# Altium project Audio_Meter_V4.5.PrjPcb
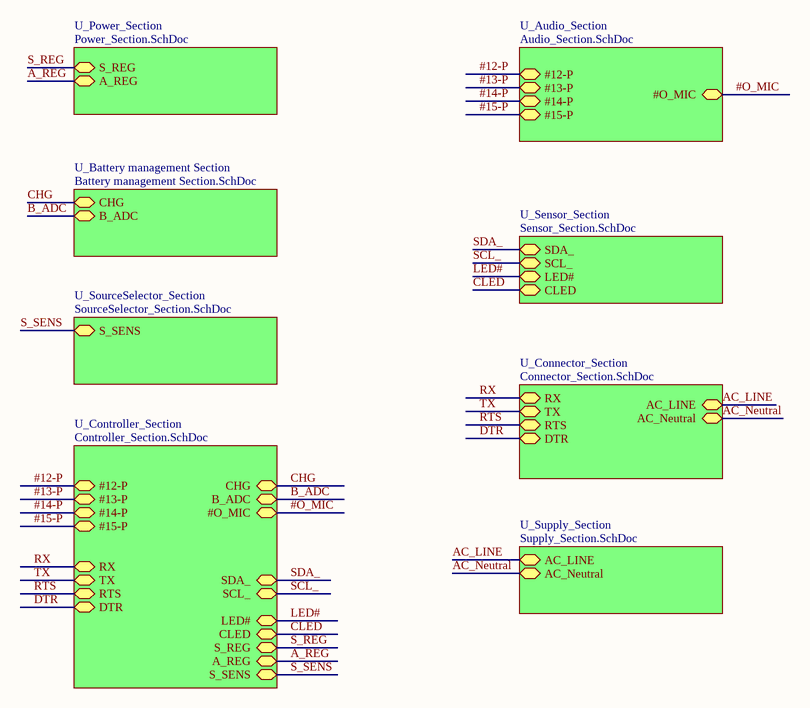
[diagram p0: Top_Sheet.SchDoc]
9 sheets, 115 parts. Net scope: hierarchical (ports join the sheet entries above them; power ports are global).
Board file: latest_Audio_Meter_V4.5.PcbDoc
Sheets:
  Top_Sheet.SchDoc
    U_Audio_Section = Audio_Section.SchDoc
    U_Connector_Section = Connector_Section.SchDoc
    U_Supply_Section = Supply_Section.SchDoc
    U_Battery management Section = Battery management Section.SchDoc
    U_Power_Section = Power_Section.SchDoc
    U_Controller_Section = Controller_Section.SchDoc
    U_SourceSelector_Section = SourceSelector_Section.SchDoc
    U_Sensor_Section = Sensor_Section.SchDoc

## Sheet Top_Sheet.SchDoc
size A; DocumentNumber: 1; SheetNumber: 1; SheetTotal: 8

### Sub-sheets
U_Audio_Section = Audio_Section.SchDoc: #O_MIC (bidir), #13-P (bidir), #14-P (bidir), #12-P (bidir), #15-P (bidir)
U_Battery management Section = Battery management Section.SchDoc: B_ADC (bidir), CHG (bidir)
U_Connector_Section = Connector_Section.SchDoc: RX (bidir), TX (bidir), RTS (bidir), DTR (bidir), AC_LINE (bidir), AC_Neutral (bidir)
U_Controller_Section = Controller_Section.SchDoc: B_ADC (bidir), CHG (bidir), #12-P (bidir), #13-P (bidir), #14-P (bidir), #15-P (bidir), #O_MIC (bidir), RX (bidir), TX (bidir), RTS (bidir), DTR (bidir), SDA_ (bidir), SCL_ (bidir), S_SENS (bidir), CLED (bidir), LED# (bidir), A_REG (bidir), S_REG (bidir)
U_Power_Section = Power_Section.SchDoc: A_REG (bidir), S_REG (bidir)
U_Sensor_Section = Sensor_Section.SchDoc: SDA_ (bidir), SCL_ (bidir), CLED (bidir), LED# (bidir)
U_SourceSelector_Section = SourceSelector_Section.SchDoc: S_SENS (bidir)
U_Supply_Section = Supply_Section.SchDoc: AC_LINE (bidir), AC_Neutral (bidir)

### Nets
#12-P: sheet U_Audio_Section/#12-P, sheet U_Controller_Section/#12-P
#13-P: sheet U_Audio_Section/#13-P, sheet U_Controller_Section/#13-P
#14-P: sheet U_Audio_Section/#14-P, sheet U_Controller_Section/#14-P
#15-P: sheet U_Audio_Section/#15-P, sheet U_Controller_Section/#15-P
#O_MIC: sheet U_Audio_Section/#O_MIC, sheet U_Controller_Section/#O_MIC
A_REG: sheet U_Power_Section/A_REG, sheet U_Controller_Section/A_REG
AC_LINE: sheet U_Connector_Section/AC_LINE, sheet U_Supply_Section/AC_LINE
AC_Neutral: sheet U_Connector_Section/AC_Neutral, sheet U_Supply_Section/AC_Neutral
B_ADC: sheet U_Battery management Section/B_ADC, sheet U_Controller_Section/B_ADC
CHG: sheet U_Battery management Section/CHG, sheet U_Controller_Section/CHG
CLED: sheet U_Controller_Section/CLED, sheet U_Sensor_Section/CLED
DTR: sheet U_Connector_Section/DTR, sheet U_Controller_Section/DTR
LED#: sheet U_Controller_Section/LED#, sheet U_Sensor_Section/LED#
RTS: sheet U_Connector_Section/RTS, sheet U_Controller_Section/RTS
RX: sheet U_Connector_Section/RX, sheet U_Controller_Section/RX
S_REG: sheet U_Power_Section/S_REG, sheet U_Controller_Section/S_REG
S_SENS: sheet U_Controller_Section/S_SENS, sheet U_SourceSelector_Section/S_SENS
SCL_: sheet U_Controller_Section/SCL_, sheet U_Sensor_Section/SCL_
SDA_: sheet U_Controller_Section/SDA_, sheet U_Sensor_Section/SDA_
TX: sheet U_Connector_Section/TX, sheet U_Controller_Section/TX

## Sheet Audio_Section.SchDoc
size A; DocumentNumber: 6; SheetNumber: 6; SheetTotal: 8
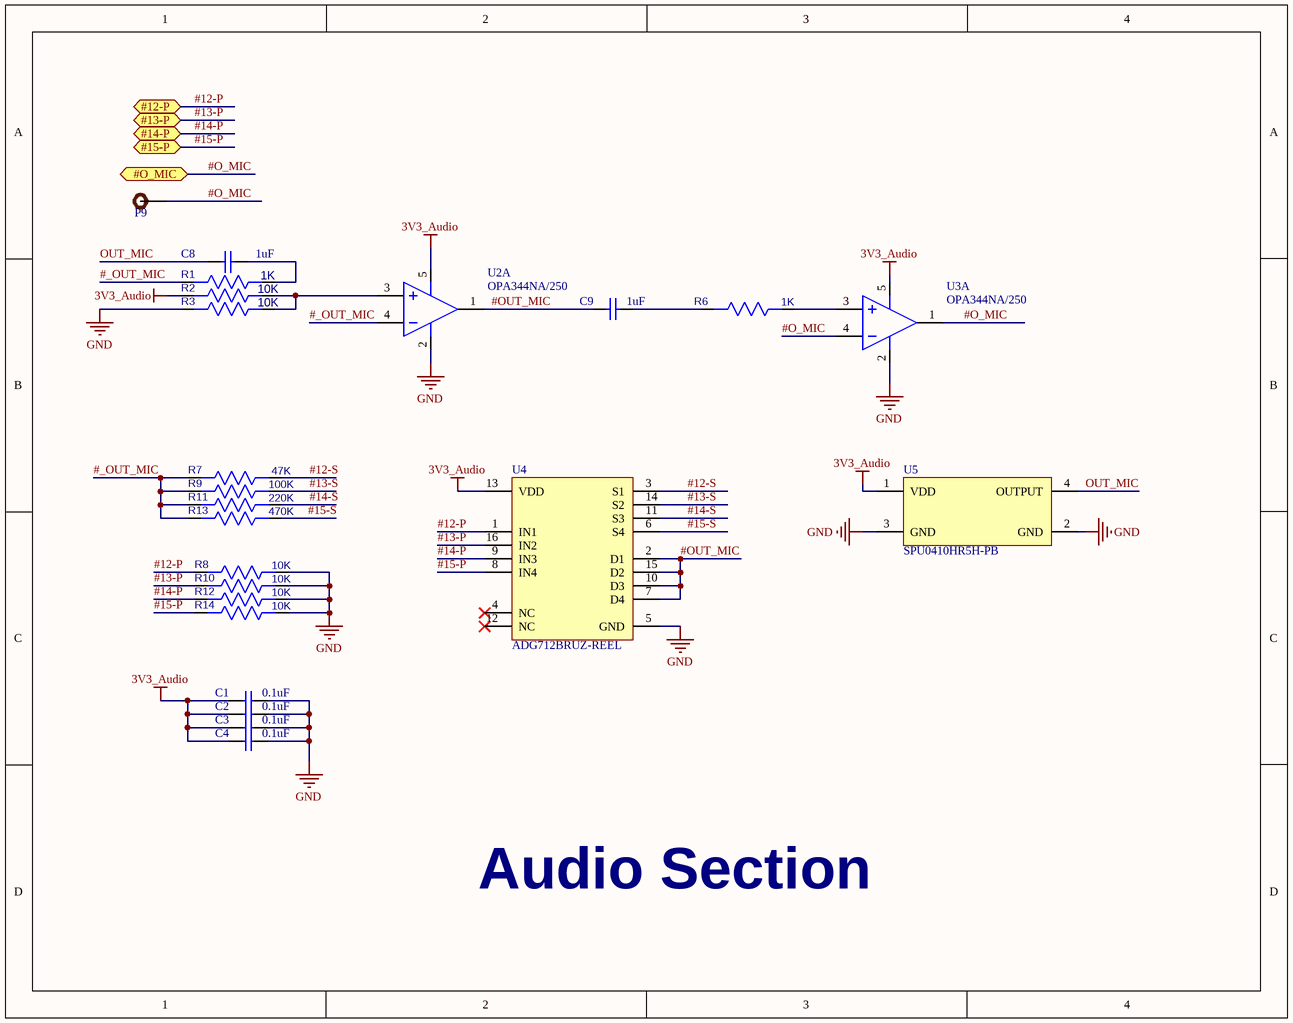
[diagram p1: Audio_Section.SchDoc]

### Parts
C1  0.1uF  [Cap0603]
C2  0.1uF  [Cap0603]
C3  0.1uF  [Cap0603]
C4  0.1uF  [Cap0603]
C8  Capacitance: 1uF  [Cap1206]  (hidden comment: 1206YC105K4T2A)
C9  Capacitance: 1uF  [Cap1206]  (hidden comment: 1206YC105K4T2A)
P9  TEST POINT  [TEST POINT]  (value not drawn)
R1  1K  [RES 0805]
R2  10K  [RES 0805]
R3  10K  [RES 0805]
R6  1K  [RES 0805]
R7  47K  [RES 0805]
R8  10K  [RES 0805]
R9  100K  [RES 0805]
R10  10K  [RES 0805]
R11  220K  [RES 0805]
R12  10K  [RES 0805]
R13  470K  [RES 0805]
R14  10K  [RES 0805]
U2A  OPA344NA/250  [SOT23-5]
U3A  OPA344NA/250  [SOT23-5]
U4  ADG712BRUZ-REEL  [16-TSSOP]
U5  SPU0410HR5H-PB  [SPU0410HR5H-PB]

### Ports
#12-P (bidir), #13-P (bidir), #14-P (bidir), #15-P (bidir), #O_MIC (bidir)

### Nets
3V3_Audio: C1.1 C2.1 C3.1 C4.1 R2.2 U2A.5(V+) U3A.5(V+) U4.13(VDD) U5.1(VDD)
GND: C1.2 C2.2 C3.2 C4.2 R3.2 R8.1 R10.1 R12.1 R14.1 U2A.2(V-) U3A.2(V-) U4.5(GND) U5.2(GND) U5.3(GND)
#12-P: R8.2 U4.1(IN1) ; port #12-P
#12-S: R7.1 U4.3(S1)
#13-P: R10.2 U4.16(IN2) ; port #13-P
#13-S: R9.1 U4.14(S2)
#14-P: R12.2 U4.9(IN3) ; port #14-P
#14-S: R11.1 U4.11(S3)
#15-P: R14.2 U4.8(IN4) ; port #15-P
#15-S: R13.1 U4.6(S4)
#_OUT_MIC: R1.2 R7.2 R9.2 R11.2 R13.2 U2A.4(IN-)
#O_MIC: P9.1 U3A.1(OUT) U3A.4(IN-) ; port #O_MIC
#OUT_MIC: C9.1 U2A.1(OUT) U4.2(D1) U4.7(D4) U4.10(D3) U4.15(D2)
OUT_MIC: C8.1 U5.4(OUTPUT)
NetC8_2: C8.2 R1.1
NetC9_2: C9.2 R6.2
NetR2_1: R2.1 R3.1 U2A.3(IN+)
NetR6_1: R6.1 U3A.3(IN+)

Not connected (* = marked no-connect by the designer): U4 4(NC)* 12(NC)*

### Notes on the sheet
- Audio Section

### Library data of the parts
C1-C4 = CC0603ZRY5V9BB104: CAP CER 0.1UF 50V Y5V 0603; Manufacturer: Yageo; Capacitance: 100nF; Tolerance: 80%
C8 C9 = 1206YC105K4T2A: CAP CER 1UF 16V X7R 1206; Manufacturer: Kyocera AVX; Tolerance: 10%
P9 = TEST POINT: Test Point ON
R1 R6 = ERJ-P06J102V: RES SMD 1K OHM 5% 1/2W 0805; Manufacturer: Panasonic; Resistance: 1kR; Power Rating: 500mW; Voltage Rating: 400V; Temperature Coefficient: 200ppm/°C; Voltage Rating (DC): 150V
R2 R3 R8 R10 R12 R14 = ERJ-P06J103V: RES SMD 10K OHM 5% 1/2W 0805; Manufacturer: Panasonic; Resistance: 10kR; Power Rating: 500mW; Voltage Rating: 400V; Temperature Coefficient: 200ppm/°C; Voltage Rating (DC): 150V
R7 = CRCW080547K0FKEAHP: RES SMD 47K OHM 1% 1/3W 0805; Manufacturer: Vishay; Power Rating: 330mW; Resistance: 47kR; Temperature Coefficient: 100ppm/°C; Voltage Rating: 150V; Max Power Dissipation: 333mW
R9 = ERJ-P06J104V: RES SMD 100K OHM 5% 1/2W 0805; Manufacturer: Panasonic; Power Rating: 500mW; Voltage Rating: 400V; Resistance: 100kR; Temperature Coefficient: 200ppm/°C; Max Power Dissipation: 250mW; Voltage Rating (DC): 150V
R11 = ERJ-P06J224V: RES SMD 220K OHM 5% 1/2W 0805; Manufacturer: Panasonic; Resistance: 220kR; Power Rating: 500mW; Voltage Rating: 150V; Temperature Coefficient: 200ppm/°C
R13 = CRCW0805470KFKEAHP: RES SMD 470K OHM 1% 1/3W 0805; Manufacturer: Vishay Dale; Resistance: 470kR; Power Rating: 330mW; Temperature Coefficient: 100ppm/°C; Max Power Dissipation: 500mW
U2A U3A = OPA344NA/250: IC OPAMP GP 1 CIRCUIT SOT23-5; Manufacturer: Texas Instruments; Nominal Supply Current: 250uA; Bandwidth: 1MHz; Min Supply Voltage: 2.7V; Max Supply Voltage: 5.5V; Voltage Gain: 122dB; Common Mode Rejection Ratio: 76dB; Number of Channels: 1; Slew Rate: 0.8V/µs; Max I/O Voltage: 1mV; Input Bias Current: 10pA; Power Supply Rejection Ratio (PSRR): 90.46dB; Output Current per Channel: 15mA; Quiescent Current: 250mA
U4 = ADG712BRUZ-REEL: IC SWITCH QUAD SPST 16TSSOP; Manufacturer: Analog Devices; Max Supply Voltage: 5.5V; Min Supply Voltage: 1.8V; Number of Inputs: 4; Max Power Dissipation: 5uW; On-State Resistance: 4R; -3db Bandwidth: 200MHz; Max Supply Current: 1uA; Turn-On Delay Time: 11ns; Turn-Off Delay Time: 6ns; Operating Supply Current: 1nA; Power Dissipation: 430mW; Supply Type: Single; Polarity: Non-Inverting; High Level Output Current: 30mA; Interface: Parallel
U5 = SPU0410HR5H-PB: SPU-TOP MIC IOT FOCUSED MIC; Manufacturer: Knowles; Shape: Rectangular; Impedance: 300R; Voltage Rating: 3.6V; Direction: Omnidirectional; Operating Supply Current: 250uA; Signal to Noise Ratio (SNR): 59dB; Output Type: Analog

## Sheet Connector_Section.SchDoc
size A; DocumentNumber: 8; SheetNumber: 8; SheetTotal: 8
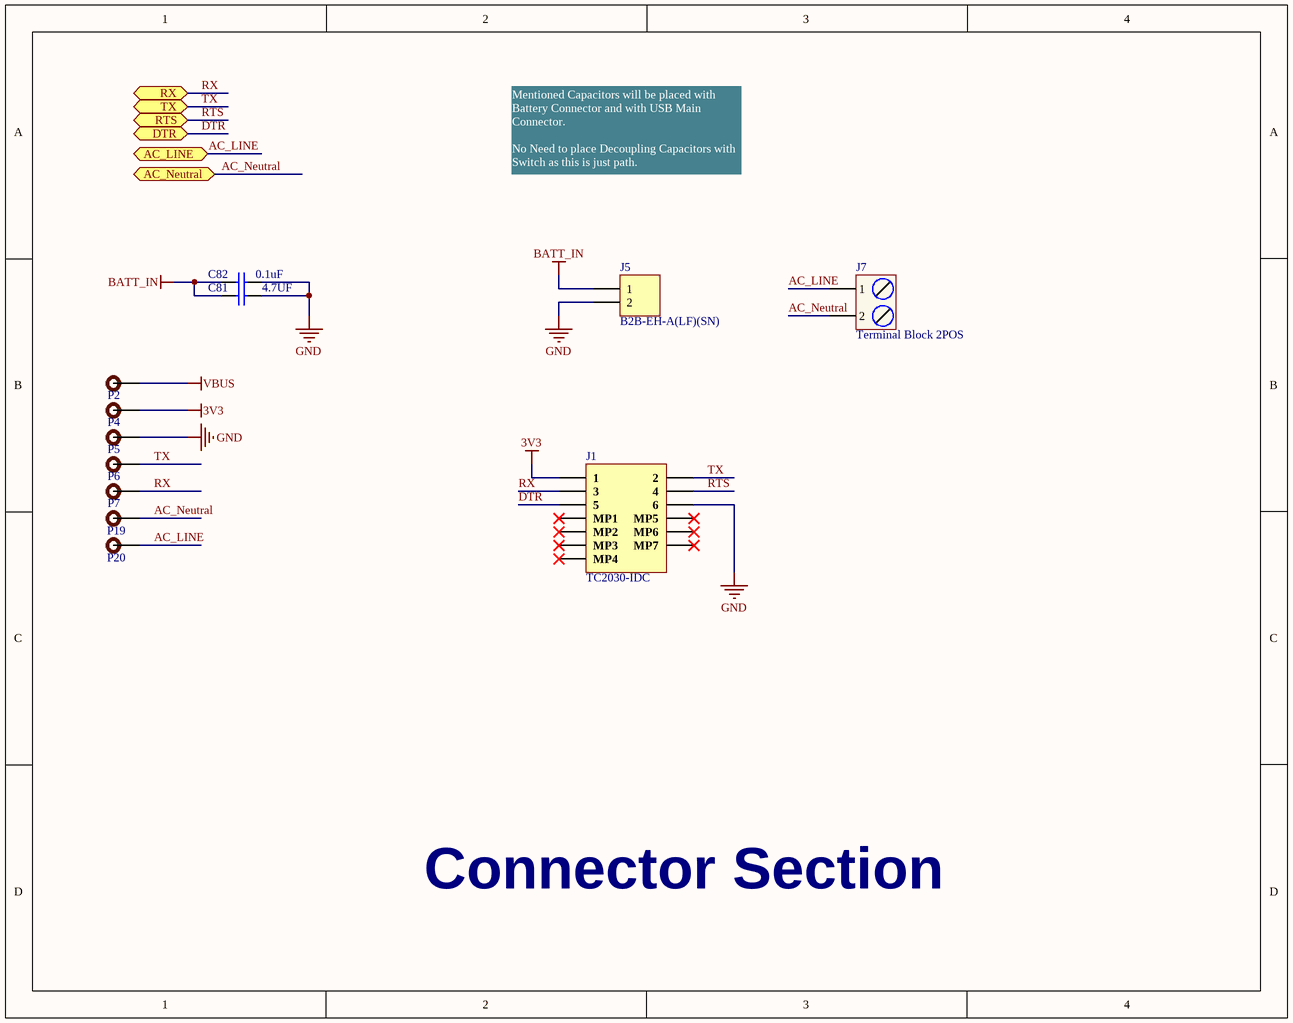
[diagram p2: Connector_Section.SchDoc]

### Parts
C81  4.7UF  [Cap0805]
C82  0.1uF  [Cap0603]
J1  TC2030-IDC  [TC2030-IDC]
J5  B2B-EH-A(LF)(SN)  [B2B-EH-A(LF)(SN)]
J7  Terminal Block 2POS  [Terminal Block 2P]
P2  TEST POINT  [TEST POINT]  (value not drawn)
P4  TEST POINT  [TEST POINT]  (value not drawn)
P5  TEST POINT  [TEST POINT]  (value not drawn)
P6  TEST POINT  [TEST POINT]  (value not drawn)
P7  TEST POINT  [TEST POINT]  (value not drawn)
P19  TEST POINT  [TEST POINT]  (value not drawn)
P20  TEST POINT  [TEST POINT]  (value not drawn)

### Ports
AC_LINE (bidir), AC_Neutral (bidir), DTR (bidir), RTS (bidir), RX (bidir), TX (bidir)

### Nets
3V3: J1.1 P4.1
BATT_IN: C81.1 C82.1 J5.1
GND: C81.2 C82.2 J1.6 J5.2 P5.1
VBUS: P2.1
AC_LINE: J7.1 P20.1 ; port AC_LINE
AC_Neutral: J7.2 P19.1 ; port AC_Neutral
DTR: J1.5 ; port DTR
RTS: J1.4 ; port RTS
RX: J1.3 P7.1 ; port RX
TX: J1.2 P6.1 ; port TX

Not connected (* = marked no-connect by the designer): J1 MP1* MP2* MP3* MP4* MP5* MP6* MP7*

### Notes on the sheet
- Mentioned Capacitors will be placed with Battery Connector and with USB Main Connector.
  No Need to place Decoupling Capacitors with Switch as this is just path.
- Connector Section

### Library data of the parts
C81 = C0805C475K4PACTU: CAP CER 4.7UF 16V 10% X5R 0805; Manufacturer: KEMET; Dielectric Material: Ceramic
C82 = CC0603ZRY5V9BB104: as C1 on sheet Audio_Section
J1 = TC2030-IDC: CABLE ADAPTER 6 POS; Manufacturer: Tag-Connect
J5 = B2B-EH-A(LF)(SN): CONN HEADER VERT 2POS 2.5MM; Manufacturer: JST; Current Rating: 3A; Voltage Rating: 250V; Contact Resistance: 20mR; Number of Positions: 2; Connector Type: Male Pin,Plug; Gender: Male
J7 = Terminal Block 2POS: TERMINAL BLOCK 2POS 5.08MM SIDE; Manufacturer: TE Connectivity; Manufacturer P/N: 1776493-2
P2 P4-P7 P19 P20 = TEST POINT: Test Point ON

## Sheet Supply_Section.SchDoc
size A4
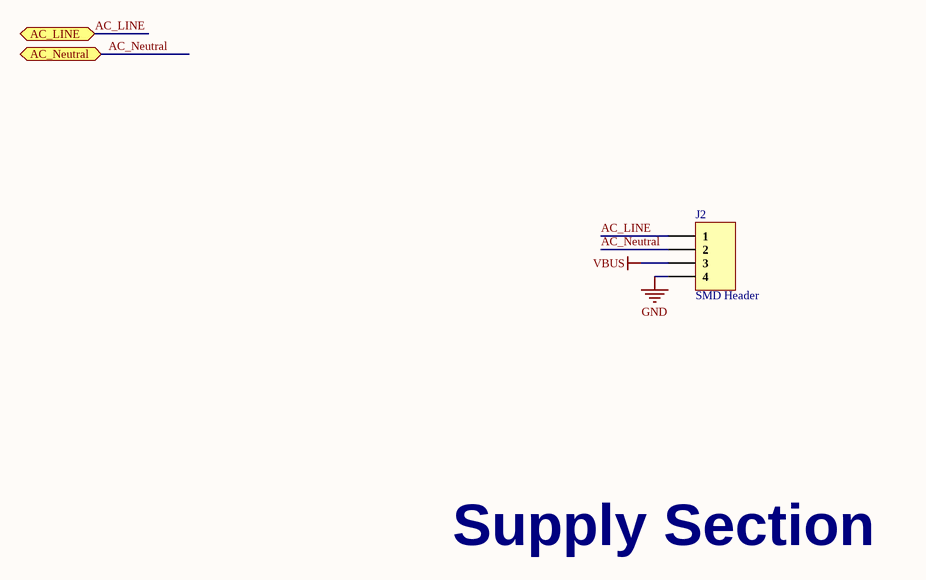
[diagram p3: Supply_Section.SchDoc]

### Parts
J2  SMD Header  [SMD Header]

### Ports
AC_LINE (bidir), AC_Neutral (bidir)

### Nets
GND: J2.4
VBUS: J2.3
AC_LINE: J2.1 ; port AC_LINE
AC_Neutral: J2.2 ; port AC_Neutral

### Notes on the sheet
- Supply Section

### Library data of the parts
J2 = SMD Header: According to module demension

## Sheet Battery management Section.SchDoc
size A; DocumentNumber: 4; SheetNumber: 4; SheetTotal: 8
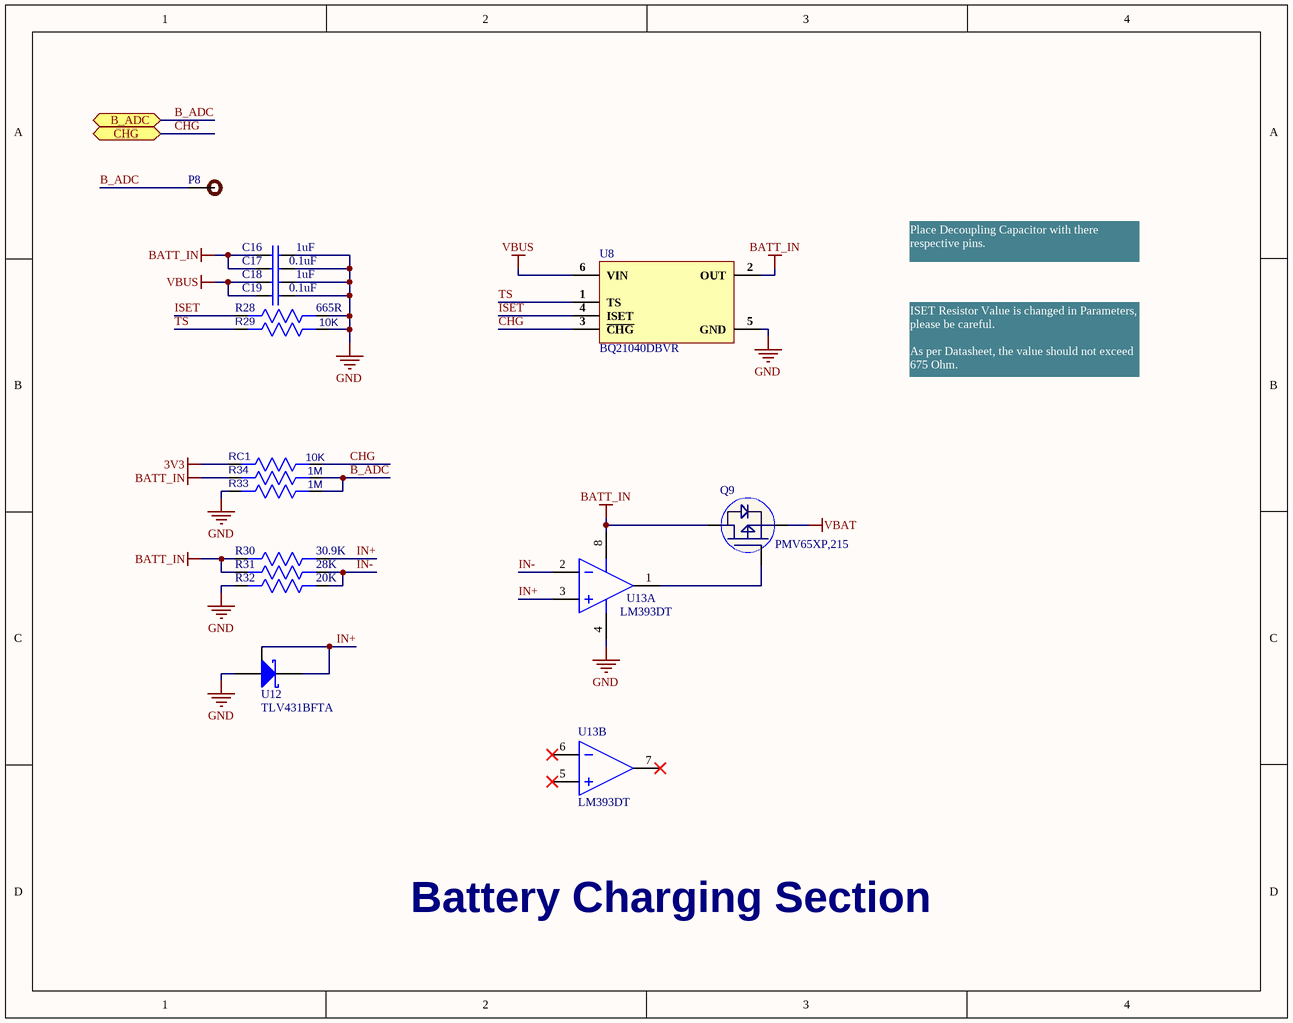
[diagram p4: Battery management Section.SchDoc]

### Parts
C16  1uF  [Cap0805]
C17  0.1uF  [Cap0603]
C18  1uF  [Cap0805]
C19  0.1uF  [Cap0603]
P8  TEST POINT  [TEST POINT]  (value not drawn)
Q9  PMV65XP,215  [SOT-23]
R28  665R  [Res0402]
R29  10K  [RES 0805]
R30  30.9K  [Res0402]
R31  28K  [Res-0201]
R32  20K  [Res-0201]
R33  1M  [RES 0805]
R34  1M  [RES 0805]
RC1  10K  [RES 0805]
U8  BQ21040DBVR  [SOT-23-6]
U12  TLV431BFTA  [SOT-23]
U13  LM393DT  [LM393DT]  (parts A,B of 2)

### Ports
B_ADC (bidir), CHG (bidir)

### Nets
3V3: RC1.2
BATT_IN: C16.1 C17.1 Q9.3(D) R30.2 R31.2 R34.2 U8.2(OUT) U13.8(V+)
GND: C16.2 C17.2 C18.2 C19.2 R28.1 R29.1 R32.2 R33.2 U8.5(GND) U12.3(ANODE) U13.4(V-)
VBAT: Q9.2(S)
VBUS: C18.1 C19.1 U8.6(VIN)
B_ADC: P8.1 R33.1 R34.1 ; port B_ADC
CHG: RC1.1 U8.3(~{CH}~{G}) ; port CHG
IN+: R30.1 U12.1(REF) U12.2(CATHODE) U13.3(IN1+)
IN-: R31.1 R32.1 U13.2(IN1-)
ISET: R28.2 U8.4(ISET)
TS: R29.2 U8.1(TS)
NetQ9_1: Q9.1(G) U13.1(OUT1)

Not connected (* = marked no-connect by the designer): U13 5(IN2+)* 6(IN2-)* 7(OUT2)*

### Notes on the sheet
- Place Decoupling Capacitor with there respective pins.
- ISET Resistor Value is changed in Parameters, please be careful.
  As per Datasheet, the value should not exceed 675 Ohm.
- Battery Charging Section

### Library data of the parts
C16 C18 = CL21B105KOFNNNG: CAP CER 1UF 16V X7R 0805; Manufacturer: Samsung; Material: Ceramic; Tolerance: 10%
C17 C19 = CC0603ZRY5V9BB104: as C1 on sheet Audio_Section
P8 = TEST POINT: Test Point ON
Q9 = PMV65XP,215: MOSFET P-CH 20V 2.8A SOT-23; Manufacturer: Nexperia
R28 = RC0402FR-07665RL: RES SMD 665 OHM 1% 1/16W 0402; Manufacturer: Yageo; Temperature Coefficient: 100ppm/°C; Power Rating: 62.5mW; Voltage Rating: 50V; Max Power Dissipation: 63mW
R29 RC1 = ERJ-P06J103V: as R2 on sheet Audio_Section
R30 = AC0402FR-0730K9L: RES SMD 30.9K OHM 1% 1/16W 0402; Manufacturer: Yageo; Power Rating: 62.5mW; Resistance: 30.9kR; Voltage Rating: 50V; Temperature Coefficient: 100ppm/°C; Max Power Dissipation: 63mW
R31 = AC0201FR-0728KL: RES SMD 28K OHM 1% 1/20W 0201; Manufacturer: Yageo; Resistance: 28kR; Max Power Dissipation: 50mW; Temperature Coefficient: 200ppm/°C
R32 = AC0201FR-0720KL: RES SMD 20K OHM 1% 1/20W 0201; Manufacturer: Yageo; Resistance: 20kR; Max Power Dissipation: 50mW; Temperature Coefficient: 200ppm/°C
R33 R34 = ERJ-P06J105V: RES SMD 1M OHM 5% 1/2W 0805; Manufacturer: Panasonic; Resistance: 1MR; Power Rating: 500mW; Voltage Rating: 400V; Temperature Coefficient: 200ppm/°C; Voltage Rating (DC): 150V
U8 = BQ21040DBVR: IC BAT CHG LI-ION 1 CELL SOT23-6; Manufacturer: Texas Instruments; Number of Cells: 1; Fault Protection: Over Voltage,Over Temperature,Short Circuit; Interface: USB,SPI; Output Type: Analog Current/Voltage; Max Charge Current: 800mA; Battery Pack Voltage: 4.2V; Max Supply Voltage: 6.45V; Number of Bits: 16; Number of D/A Converters: 4; Settling Time: 30us; Differential Output: No
U12 = TLV431BFTA: IC VREF SHUNT 18V 0.5% SOT23; Manufacturer: Diodes Zetex; Max Input Voltage: 20V; Max Output Current: 15mA; Reference Type: Shunt,Adjustable; Min Output Voltage: 1.24V; Cathode Current: 100uA; Output Type: Adjustable
U13 = LM393DT: IC COMPARATOR LP DUAL 8-SOIC; Manufacturer: STMicroelectronics; Nominal Supply Current: 1mA; Voltage Gain: 106.02dB; Min Supply Voltage: 2V; Max Supply Voltage: 36V; Min Dual Supply Voltage: 1V; Max Dual Supply Voltage: 18V; Number of Channels: 2; Output Current: 18mA; Quiescent Current: 2.5mA; Input Offset Voltage (Vos): 5mV; Input Bias Current: 250nA; Output Current per Channel: 100pA; Response Time: 1.3us; Output Type: TTL; Operating Supply Voltage: 28V; Dual Supply Voltage: 9V; Max Power Dissipation: 710mW; Natural Thermal Resistance: 125°C/W

## Sheet Power_Section.SchDoc
size A4; DocumentNumber: 2; SheetNumber: 2; SheetTotal: 8
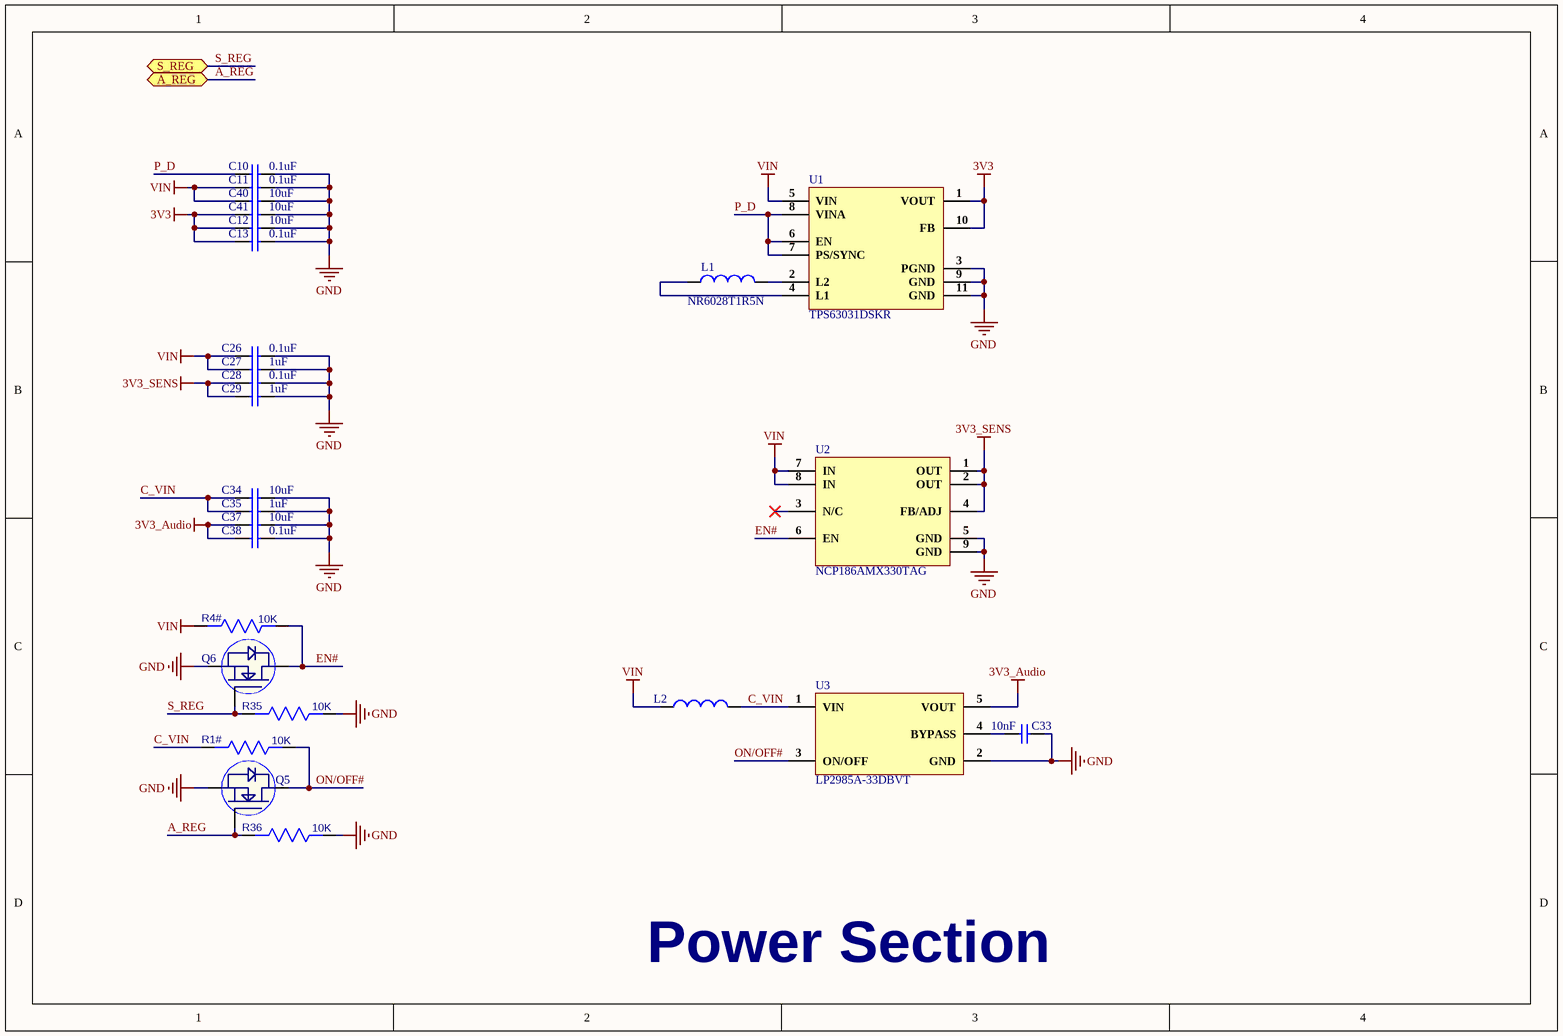
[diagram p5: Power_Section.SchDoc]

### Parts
C10  0.1uF  [Cap0603]
C11  0.1uF  [Cap0603]
C12  10uF  [Cap0603]
C13  0.1uF  [Cap0603]
C26  0.1uF  [Cap0603]
C27  1uF  [Cap0805]
C28  0.1uF  [Cap0603]
C29  1uF  [Cap0805]
C33  10nF  [CAP 0201]
C34  10uF  [Cap0603]
C35  1uF  [Cap0805]
C37  10uF  [Cap0603]
C38  0.1uF  [Cap0603]
C40  10uF  [Cap0603]
C41  10uF  [Cap0603]
L1  NR6028T1R5N  [NR6028T1R5N]
L2  BLM18SG121TN1D  [IND 0603]  (value not drawn)
Q5  BSS138LT1G  [SOT-23]  (value not drawn)
Q6  BSS138LT1G  [SOT-23]  (value not drawn)
R1#  10K  [RES 0805]
R4#  10K  [RES 0805]
R35  10K  [RES 0805]
R36  10K  [RES 0805]
U1  TPS63031DSKR  [TPS63031DSKR]
U2  NCP186AMX330TAG  [NCP186AMX330TAG]
U3  LP2985A-33DBVT  [SOT23-5]

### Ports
A_REG (bidir), S_REG (bidir)

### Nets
3V3: C12.1 C13.1 C41.1 U1.1(VOUT) U1.10(FB)
3V3_Audio: C37.1 C38.1 U3.5(VOUT)
3V3_SENS: C28.1 C29.1 U2.1(OUT) U2.2(OUT) U2.4(FB/ADJ)
GND: C10.2 C11.2 C12.2 C13.2 C26.2 C27.2 C28.2 C29.2 C33.2 C34.2 C35.2 C37.2 C38.2 C40.2 C41.2 Q5.2(S) Q6.2(S) R35.2 R36.2 U1.3(PGND) U1.9(GND) U1.11(GND) U2.5(GND) U2.9(GND) U3.2(GND)
VIN: C11.1 C26.1 C27.1 C40.1 L2.1 R4#.2 U1.5(VIN) U2.7(IN) U2.8(IN)
A_REG: Q5.1(G) R36.1 ; port A_REG
C_VIN: C34.1 C35.1 L2.2 R1#.2 U3.1(VIN)
EN#: Q6.3(D) R4#.1 U2.6(EN)
ON/OFF#: Q5.3(D) R1#.1 U3.3(ON/OFF)
P_D: C10.1 U1.6(EN) U1.7(PS/SYNC) U1.8(VINA)
S_REG: Q6.1(G) R35.1 ; port S_REG
NetC33_1: C33.1 U3.4(BYPASS)
NetL1_1: L1.1 U1.4(L1)
NetL1_2: L1.2 U1.2(L2)

Not connected (* = marked no-connect by the designer): U2 3(N/C)*

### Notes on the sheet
- Power Section

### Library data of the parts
C10 C11 C13 C26 C28 C38 = CC0603ZRY5V9BB104: as C1 on sheet Audio_Section
C12 C34 C37 C40 C41 = C1608X5R1E106M080AC: CAP CER 10UF 25V X5R 0603; Manufacturer: TDK; Dielectric Material: Ceramic; Tolerance: 20%
C27 C29 C35 = CL21B105KOFNNNG: as C16 on sheet Battery management Section
C33 = UMK063BJ103KP-F: CAP CER 10000PF 50V X5R 0201; Manufacturer: Taiyo Yuden; Tolerance: 10%
L1 = NR6028T1R5N: FIXED IND 1.5UH 4.2A 20.8 MOHM; Manufacturer: Taiyo Yuden; Manufacturer Part Number: NR6028T470M; Core Material: Ferrite; Tolerance: 20%; Current Rating: 920mA; Saturation Current: 950mA; Shielding: Shielded; Self Resonant Frequency: 8MHz; Inductance: 47uh; DC Resistance (DCR): 390mR; Test Frequency: 100kHz
L2 = BLM18SG121TN1D: FERRITE BEAD 120 OHM 0603 1LN; Manufacturer: Murata; Material: Steel,Ferrite; Tolerance: 25%; Impedance: 120R; DC Resistance (DCR): 25mR; Max DC Current: 3A; Number of Lines: 1; Test Frequency: 100MHz; Shielding: Unshielded
Q5 Q6 = BSS138LT1G: MOSFET N-CH 50V 200MA SOT-23; Manufacturer: ON Semiconductor; Gate to Source Voltage (Vgs): 20V; Nominal Vgs: 1.5V; Rds On Max: 3.5R; Input Capacitance: 50pF; Number of Elements: 1; Max Power Dissipation: 225mW; Turn-Off Delay Time: 20ns; Element Configuration: Single
R1# R4# R35 R36 = ERJ-P06J103V: as R2 on sheet Audio_Section
U1 = TPS63031DSKR: Conv DC-DC 1.8V to 5.5V Non-Inv/Inv/Step Up/Step Down Single-Out 3.3V 0.8A 10-Pin WSON; Manufacturer: Texas Instruments; Switching Frequency: 2.4MHz; Output Current: 800mA; Number of Outputs: 1; Synchronous Rectifier: Yes; Quiescent Current: 25uA; Output Type: Fixed; Efficiency: 96%; Topology: Buck-Boost; Output Configuration: Positive
U2 = NCP186AMX330TAG: IC REG LINEAR 3.3V 1A 8XDFN; Manufacturer: ON Semiconductor; Dropout Voltage: 95mV; Number of Regulators: 1; Min Current Limit: 1.1A
U3 = LP2985A-33DBVT: IC REG LINEAR 3.3V 150MA SOT23-5; Manufacturer: Texas Instruments; Number of Outputs: 1; Min Input Voltage: 2.2V; Max Input Voltage: 16V; Dropout Voltage: 280mV; Input Bias Current: 850uA; Polarity: Positive; Output Voltage Accuracy: 1%; Output Type: Fixed

## Sheet Controller_Section.SchDoc
size A; DocumentNumber: 5; SheetNumber: 5; SheetTotal: 8
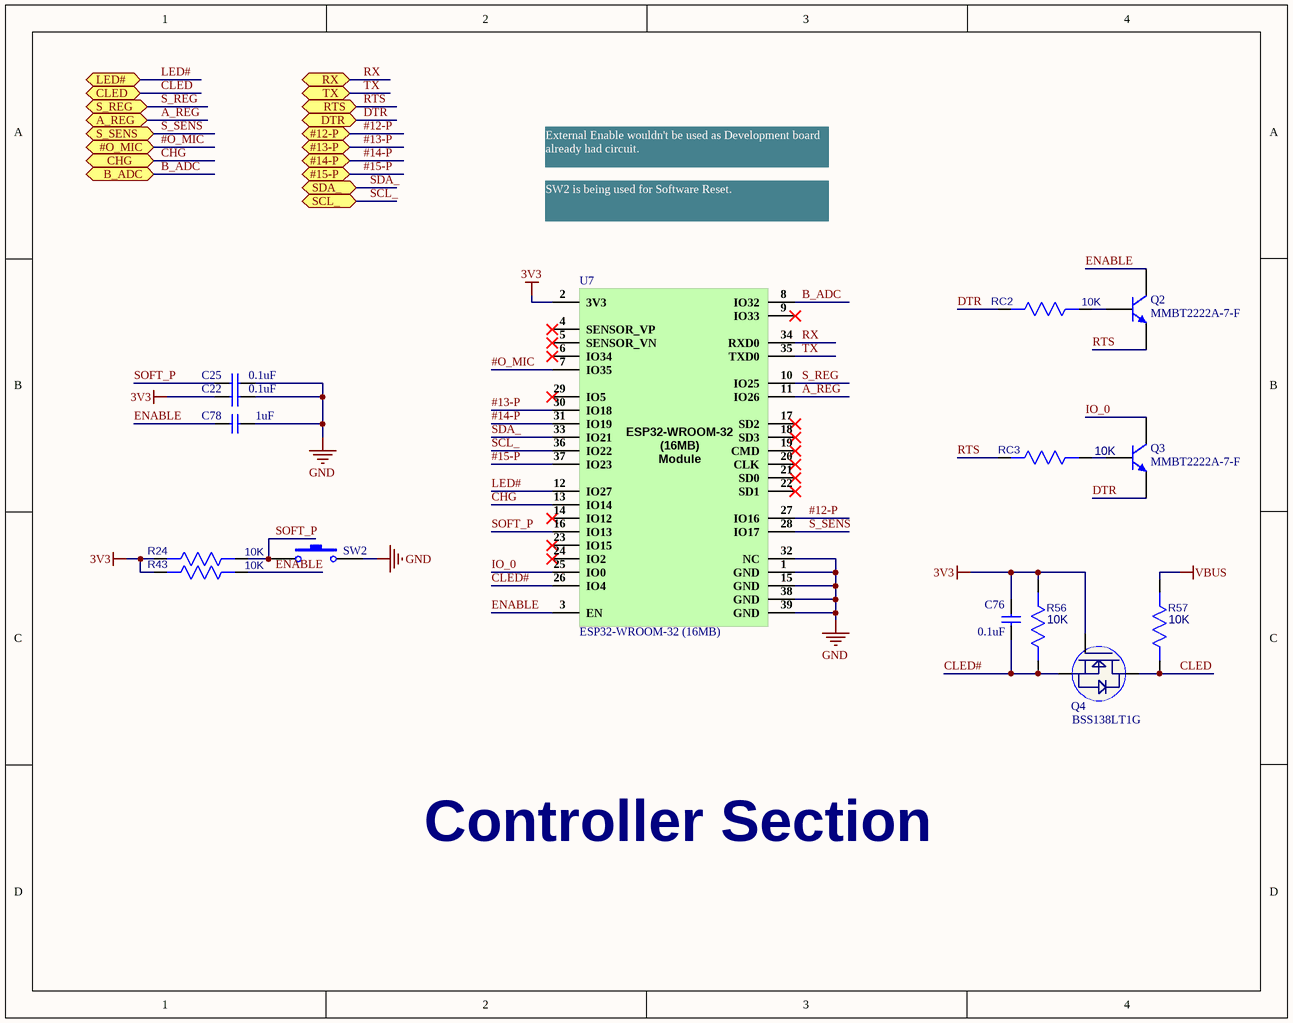
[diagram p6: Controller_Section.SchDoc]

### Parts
C22  0.1uF  [Cap0603]
C25  0.1uF  [Cap0603]
C76  0.1uF  [Cap0603]
C78  1uF  [Cap0805]
Q2  MMBT2222A-7-F  [SOT-23]
Q3  MMBT2222A-7-F  [SOT-23]
Q4  BSS138LT1G  [SOT-23]
R24  10K  [RES 0805]
R43  10K  [RES 0805]
R56  10K  [RES 0805]
R57  10K  [RES 0805]
RC2  10K  [RES 0805]
RC3  10K  [RES 0805]
SW2  Switch  [KSS221GLFS]  (value not drawn)
U7  ESP32-WROOM-32 (16MB)  [ESP32-WROOM-32 (16MB)]

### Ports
#12-P (bidir), #13-P (bidir), #14-P (bidir), #15-P (bidir), #O_MIC (bidir), A_REG (bidir), B_ADC (bidir), CHG (bidir), CLED (bidir), DTR (bidir), LED# (bidir), RTS (bidir), RX (bidir), S_REG (bidir), S_SENS (bidir), SCL_ (bidir), SDA_ (bidir), TX (bidir)

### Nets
3V3: C22.1 C76.1 Q4.1(G) R24.2 R43.2 R56.1 U7.2(3V3)
GND: C22.2 C25.2 C78.2 SW2.2 U7.1(GND) U7.15(GND) U7.32(NC) U7.38(GND) U7.39(GND)
VBUS: R57.1
#12-P: U7.27(IO16) ; port #12-P
#13-P: U7.30(IO18) ; port #13-P
#14-P: U7.31(IO19) ; port #14-P
#15-P: U7.37(IO23) ; port #15-P
#O_MIC: U7.7(IO35) ; port #O_MIC
A_REG: U7.11(IO26) ; port A_REG
B_ADC: U7.8(IO32) ; port B_ADC
CHG: U7.13(IO14) ; port CHG
CLED: Q4.3(D) R57.2 ; port CLED
CLED#: C76.2 Q4.2(S) R56.2 U7.26(IO4)
DTR: Q3.2(E) RC2.2 ; port DTR
ENABLE: C78.1 Q2.3(C) R43.1 U7.3(EN)
IO_0: Q3.3(C) U7.25(IO0)
LED#: U7.12(IO27) ; port LED#
RTS: Q2.2(E) RC3.2 ; port RTS
RX: U7.34(RXD0) ; port RX
S_REG: U7.10(IO25) ; port S_REG
S_SENS: U7.28(IO17) ; port S_SENS
SCL_: U7.36(IO22) ; port SCL_
SDA_: U7.33(IO21) ; port SDA_
SOFT_P: C25.1 R24.1 SW2.1 U7.16(IO13)
TX: U7.35(TXD0) ; port TX
NetQ2_1: Q2.1(B) RC2.1
NetQ3_1: Q3.1(B) RC3.1

Not connected (* = marked no-connect by the designer): U7 4(SENSOR_VP)* 5(SENSOR_VN)* 6(IO34)* 9(IO33)* 14(IO12)* 17(SD2)* 18(SD3)* 19(CMD)* 20(CLK)* 21(SD0)* 22(SD1)* 23(IO15)* 24(IO2)* 29(IO5)*

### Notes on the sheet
- External Enable wouldn't be used as Development board already had circuit.
- SW2 is being used for Software Reset.
- Controller Section

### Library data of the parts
C22 C25 C76 = CC0603ZRY5V9BB104: as C1 on sheet Audio_Section
C78 = CL21B105KOFNNNG: as C16 on sheet Battery management Section
Q2 Q3 = MMBT2222A-7-F: TRANS NPN 40V 0.6A SMD SOT23-3; Manufacturer: Diodes; Max Power Dissipation: 300mW; Collector Base Voltage (VCBO): 75V; Max Collector Current: 600mA; hFE Min: 100; Frequency: 300MHz; Number of Elements: 1; Emitter Base Voltage (VEBO): 6V; Collector Emitter Saturation Voltage: 1V; Power Dissipation: 350mW; Element Configuration: Single; Current: 1A
Q4 = BSS138LT1G: as Q5 on sheet Power_Section
R24 R43 R56 R57 RC2 RC3 = ERJ-P06J103V: as R2 on sheet Audio_Section
SW2 = KSS221GLFS: Tactile Switch SPST-NO Side Actuated Surface Mount, Right Angle; Manufacturer: ITT C&K; Mechanical Life: 100000Cycles; Throw Configuration: SPST; Operating Force: 2N; Max Current Rating: 50mA; Max Voltage Rating (DC): 32V; Contact Resistance: 100mR; Power Rating: 1W; Illumination Type: Non-Illuminated,Illuminated; Insulation Resistance: 1GR; Switch Travel: 0.3mm; Switch Function: Off-Mom; Actuator Length: 0.8mm; IP Rating: IP40
U7 = ESP32-WROOM-32 (16MB): WIFI MODULE 128MBITS SPI FLASH; Manufacturer: Espressif Systems; Manufacturer Part Number: ESP32-WROOM-32D(16MB); Interface: I2C,SPI,GPIO,PWM,SDIO,UART; Frequency: 2.5GHz; Data Rate: 150Mbps; Sensitivity: -98dBm; Memory Size: 536KB

## Sheet SourceSelector_Section.SchDoc
size A4
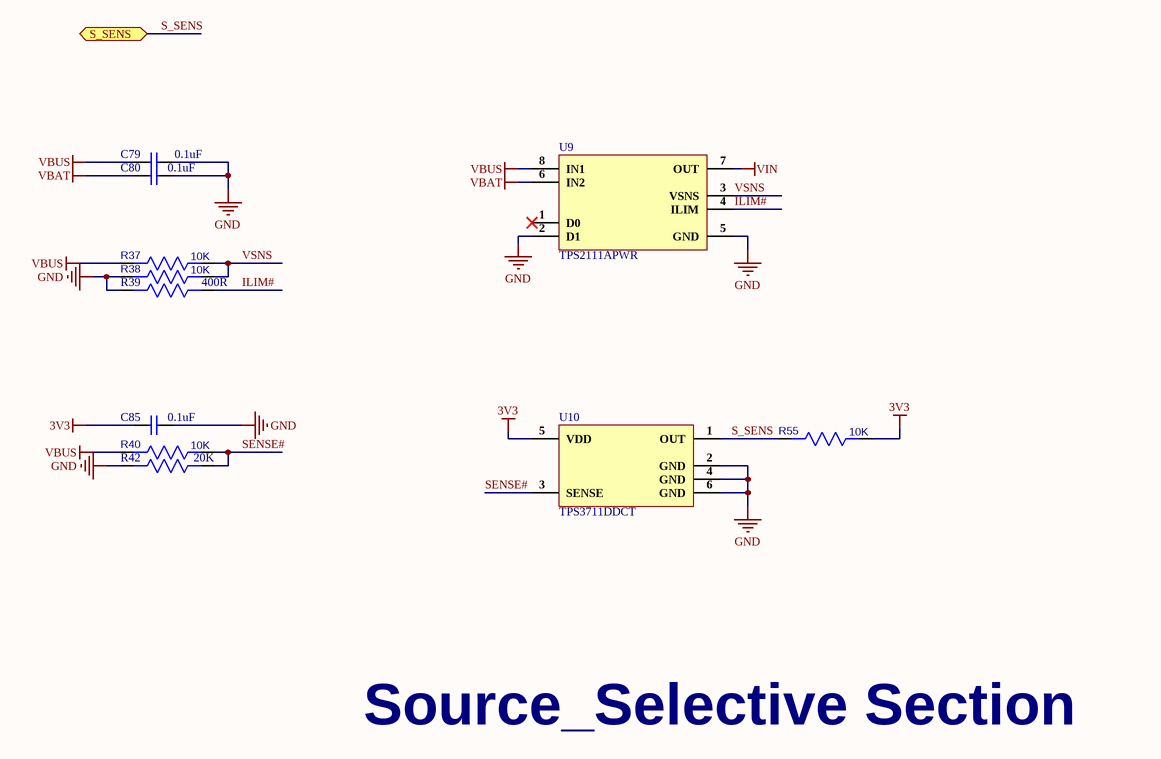
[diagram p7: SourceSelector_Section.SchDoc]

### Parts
C79  0.1uF  [Cap0603]
C80  0.1uF  [Cap0603]
C85  0.1uF  [Cap0603]
R37  10K  [RES 0805]
R38  10K  [RES 0805]
R39  400R  [Res0603]
R40  10K  [RES 0805]
R42  20K  [Res-0201]
R55  10K  [RES 0805]
U9  TPS2111APWR  [8-TSSOP]
U10  TPS3711DDCT  [SOT-23-6]

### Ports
S_SENS (bidir)

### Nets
3V3: C85.1 R55.1 U10.5(VDD)
GND: C79.2 C80.2 C85.2 R38.1 R39.2 R42.2 U9.2(D1) U9.5(GND) U10.2(GND) U10.4(GND) U10.6(GND)
VBAT: C80.1 U9.6(IN2)
VBUS: C79.1 R37.2 R40.2 U9.8(IN1)
VIN: U9.7(OUT)
ILIM#: R39.1 U9.4(ILIM)
S_SENS: R55.2 U10.1(OUT) ; port S_SENS
SENSE#: R40.1 R42.1 U10.3(SENSE)
VSNS: R37.1 R38.2 U9.3(VSNS)

Not connected (* = marked no-connect by the designer): U9 1(D0)*

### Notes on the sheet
- Source_Selective Section

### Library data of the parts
C79 C80 C85 = CC0603ZRY5V9BB104: as C1 on sheet Audio_Section
R37 R38 R40 R55 = ERJ-P06J103V: as R2 on sheet Audio_Section
R39 = PAT0603E4000BST1: RES SMD 400 OHM 0.1% 0.15W 0603; Manufacturer: Vishay Dale Thin Film; Power Rating: 150mW; Voltage Rating: 75V; Temperature Coefficient: 25ppm/°C
R42 = AC0201FR-0720KL: as R32 on sheet Battery management Section
U9 = TPS2111APWR: IC OR CTRLR SRC SELECT 8TSSOP; Manufacturer: Texas Instruments; Number of Outputs: 1; Output Current: 1.25A; Number of Inputs: 2; Max Input Voltage: 5.5V; Min Input Voltage: 2.8V; Turn-On Delay Time: 1ms; Turn-Off Delay Time: 5ms; Operating Supply Current: 55uA; Max Power Dissipation: 387mW; On-State Resistance: 84mR; Output Voltage: 6V
U10 = TPS3711DDCT: IC SUPERVISOR 1 CHANNEL TSOT23-6; Manufacturer: Texas Instruments; Number of Voltages Monitored: 1; Threshold Voltage: 400mV; Min Supply Voltage: 1.8V; Max Supply Voltage: 36V; Quiescent Current: 7uA

## Sheet Sensor_Section.SchDoc
size A4; DocumentNumber: 7; SheetNumber: 7; SheetTotal: 8
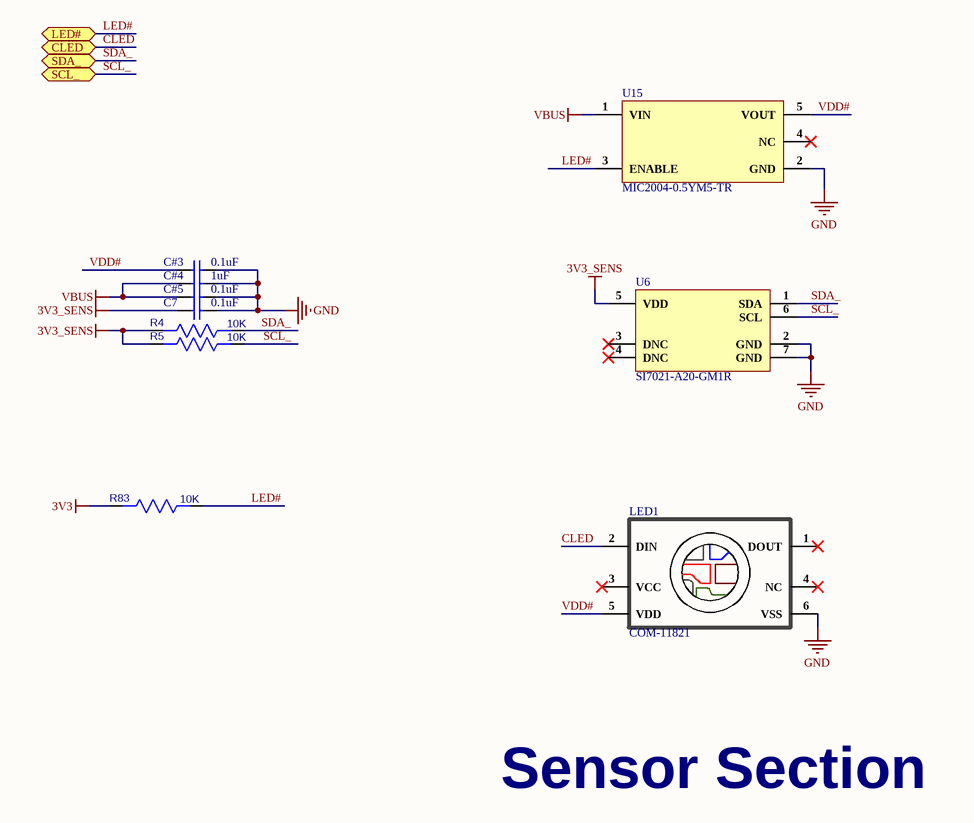
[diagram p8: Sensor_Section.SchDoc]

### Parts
C7  0.1uF  [Cap0603]
C#3  0.1uF  [Cap0603]
C#4  1uF  [Cap0805]
C#5  0.1uF  [Cap0603]
LED1  COM-11821  [COM-11821]
R4  10K  [RES 0805]
R5  10K  [RES 0805]
R83  10K  [RES 0805]
U6  SI7021-A20-GM1R  [SI7021-A20-GM1R]
U15  MIC2004-0.5YM5-TR  [SOT23-5]

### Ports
CLED (bidir), LED# (bidir), SCL_ (bidir), SDA_ (bidir)

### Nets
3V3: R83.1
3V3_SENS: C7.1 R4.2 R5.2 U6.5(VDD)
GND: C7.2 C#3.2 C#4.2 C#5.2 LED1.6(VSS) U6.2(GND) U6.7(GND) U15.2(GND)
VBUS: C#4.1 C#5.1 U15.1(VIN)
CLED: LED1.2(DIN) ; port CLED
LED#: R83.2 U15.3(ENABLE) ; port LED#
SCL_: R5.1 U6.6(SCL) ; port SCL_
SDA_: R4.1 U6.1(SDA) ; port SDA_
VDD#: C#3.1 LED1.5(VDD) U15.5(VOUT)

Not connected (* = marked no-connect by the designer): LED1 1(DOUT)* 3(VCC)* 4(NC)*; U6 3(DNC)* 4(DNC)*; U15 4(NC)*

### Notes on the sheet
- Sensor Section

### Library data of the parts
C7 C#3 C#5 = CC0603ZRY5V9BB104: as C1 on sheet Audio_Section
C#4 = CL21B105KOFNNNG: CAP CER 1UF 16V X7R 0805; Manufacturer: Samsung; Tolerance: 10%
LED1 = COM-11821: ADDRESS LED DISCRETE SERIAL RGB; Manufacturer: SparkFun; Color: Blue,Green,Red; Number of LEDs: 1
R4 R5 R83 = ERJ-P06J103V: as R2 on sheet Audio_Section
U6 = SI7021-A20-GM1R: SENS HUMID/TEMP 3.6V I2C 2% 6DFN; Manufacturer: Silicon Labs; Response Time: 18s; Accuracy: 3%; Sensor Type: Temperature; Output Type: I2C,Digital
U15 = MIC2004-0.5YM5-TR: IC PWR SWITCH P-CHAN 1:1 SOT23-5; Manufacturer: Microchip

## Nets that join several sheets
3V3: Connector_Section (J1.1 P4.1), Battery management Section (RC1.2), Power_Section (5 pins), Controller_Section (7 pins), SourceSelector_Section (C85.1 R55.1 U10.5), Sensor_Section (R83.1)
3V3_Audio: Audio_Section (9 pins), Power_Section (C37.1 C38.1 U3.5)
3V3_SENS: Power_Section (5 pins), Sensor_Section (C7.1 R4.2 R5.2 U6.5)
BATT_IN: Connector_Section (C81.1 C82.1 J5.1), Battery management Section (8 pins)
GND: Audio_Section (14 pins), Connector_Section (5 pins), Supply_Section (J2.4), Battery management Section (11 pins), Power_Section (25 pins), Controller_Section (9 pins), SourceSelector_Section (11 pins), Sensor_Section (8 pins)
VBAT: Battery management Section (Q9.2), SourceSelector_Section (C80.1 U9.6)
VBUS: Connector_Section (P2.1), Supply_Section (J2.3), Battery management Section (C18.1 C19.1 U8.6), Controller_Section (R57.1), SourceSelector_Section (C79.1 R37.2 R40.2 U9.8), Sensor_Section (C#4.1 C#5.1 U15.1)
VIN: Power_Section (9 pins), SourceSelector_Section (U9.7)
#12-P: Audio_Section (R8.2 U4.1), Controller_Section (U7.27)
#13-P: Audio_Section (R10.2 U4.16), Controller_Section (U7.30)
#14-P: Audio_Section (R12.2 U4.9), Controller_Section (U7.31)
#15-P: Audio_Section (R14.2 U4.8), Controller_Section (U7.37)
#O_MIC: Audio_Section (P9.1 U3A.1 U3A.4), Controller_Section (U7.7)
A_REG: Power_Section (Q5.1 R36.1), Controller_Section (U7.11)
AC_LINE: Connector_Section (J7.1 P20.1), Supply_Section (J2.1)
AC_Neutral: Connector_Section (J7.2 P19.1), Supply_Section (J2.2)
B_ADC: Battery management Section (P8.1 R33.1 R34.1), Controller_Section (U7.8)
CHG: Battery management Section (RC1.1 U8.3), Controller_Section (U7.13)
CLED: Controller_Section (Q4.3 R57.2), Sensor_Section (LED1.2)
DTR: Connector_Section (J1.5), Controller_Section (Q3.2 RC2.2)
LED#: Controller_Section (U7.12), Sensor_Section (R83.2 U15.3)
RTS: Connector_Section (J1.4), Controller_Section (Q2.2 RC3.2)
RX: Connector_Section (J1.3 P7.1), Controller_Section (U7.34)
S_REG: Power_Section (Q6.1 R35.1), Controller_Section (U7.10)
S_SENS: Controller_Section (U7.28), SourceSelector_Section (R55.2 U10.1)
SCL_: Controller_Section (U7.36), Sensor_Section (R5.1 U6.6)
SDA_: Controller_Section (U7.33), Sensor_Section (R4.1 U6.1)
TX: Connector_Section (J1.2 P6.1), Controller_Section (U7.35)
